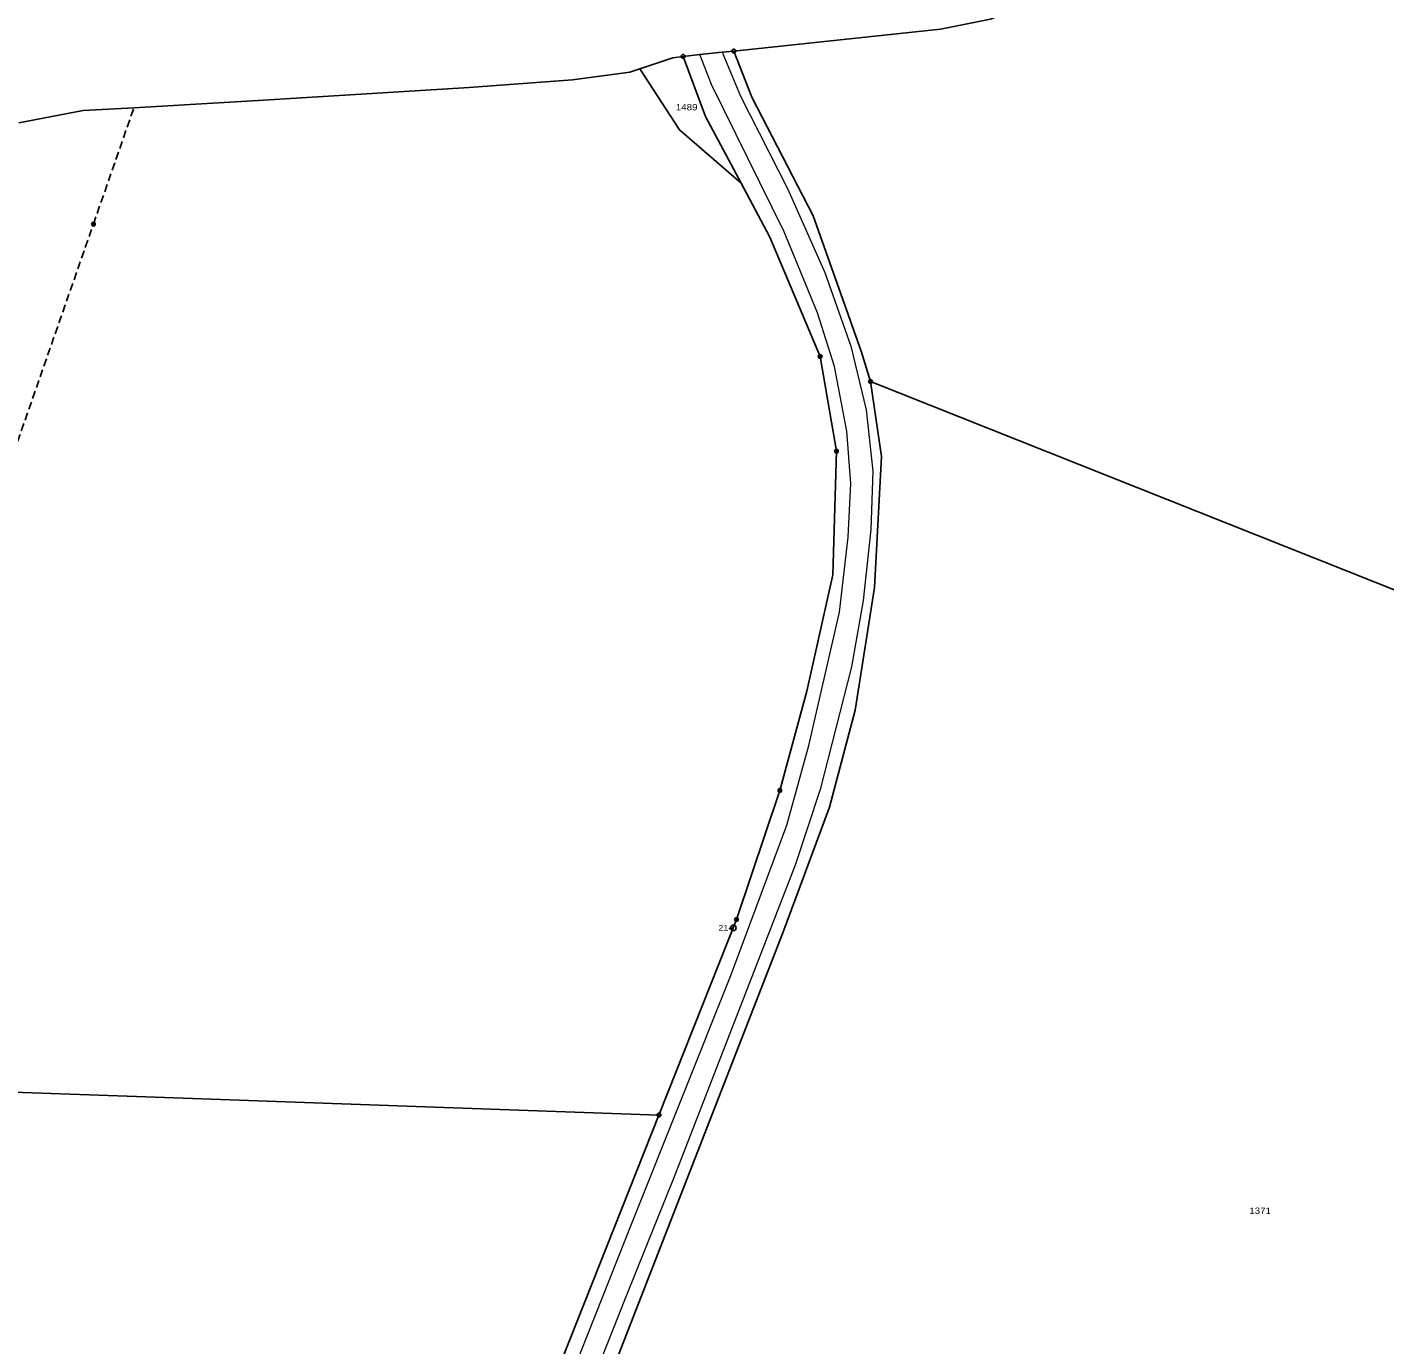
# Model space of a CAD drawing. Extents: x -872229 to -869198, y -1075981 to -1074329.
# Drawn here: x -871207 to -870843.3, y -1074936.4 to -1074583.6 of the extents above; entities that cross this region are included whole.
import ezdxf
from ezdxf.enums import TextEntityAlignment as Align

# ---------------------------------------------------------------- set-up
doc = ezdxf.new("R2010")
doc.units = 0
doc.header["$LTSCALE"] = 0.68
doc.linetypes.add('MEDIUM_DASHED', pattern=[4.5, 3, -1.5])
for name, color, linetype, lineweight in [('1', 7, 'Continuous', 25), ('4', 7, 'Continuous', 13), ('6', 7, 'Continuous', 25), ('8', 7, 'Continuous', 25)]:
    doc.layers.add(name, color=color, linetype=linetype, lineweight=lineweight)
doc.layers.add('2', color=7, linetype='Continuous')

msp = doc.modelspace()

# ---------------------------------------------------------------- linework, layer by layer
at = {"layer": '1'}
for points in [[(-870848.41, -1074534.87), (-870883.9, -1074554.93), (-870908.43, -1074563.86), (-870934.77, -1074575.4), (-870948.95, -1074581.46), (-870962.37, -1074584.16), (-871017.7, -1074589.98)], [(-871031.28, -1074591.41), (-871034.01, -1074591.76), (-871042.88, -1074594.72)], [(-871017.7, -1074589.98), (-871020.82, -1074590.31), (-871026.85, -1074590.94), (-871031.28, -1074591.41)], [(-871015.72, -1074625.4), (-871025.25, -1074607.47), (-871031.28, -1074591.41)], [(-871017.7, -1074589.98), (-871012.91, -1074602.34), (-870996.45, -1074634.07), (-870983.56, -1074670.35), (-870981.09, -1074678.49)], [(-871042.88, -1074594.72), (-871045.55, -1074595.6), (-871060.96, -1074597.73), (-871088.61, -1074599.78), (-871145.12, -1074603.23), (-871154.19, -1074603.78), (-871178.39, -1074605.16), (-871192.01, -1074605.93), (-871209.25, -1074609.21)], [(-871015.72, -1074625.4), (-871032.24, -1074611.11), (-871042.88, -1074594.72)], [(-871037.76, -1074874.85), (-871017, -1074822.52), (-871005.37, -1074787.95), (-870998.12, -1074761.36), (-870991.22, -1074730.22), (-870990.23, -1074697.13), (-870994.58, -1074671.74), (-871008.06, -1074639.82), (-871015.72, -1074625.4)], [(-870981.09, -1074678.49), (-870978.14, -1074698.51), (-870980.02, -1074733.6), (-870985.23, -1074766.42), (-870992.05, -1074792.43), (-871004.56, -1074826.1), (-871074.68, -1075006.03), (-871079.84, -1075019.17), (-871088.25, -1075040.59), (-871096.99, -1075058.79)], [(-870634.05, -1074816.48), (-870806.04, -1074748.1), (-870981.09, -1074678.49)], [(-871282.11, -1074866.22), (-871180.17, -1074869.82), (-871037.76, -1074874.85)], [(-871098, -1075028.09), (-871087.54, -1075000.31), (-871037.76, -1074874.85)]]:
    msp.add_lwpolyline(points, dxfattribs=at)
at = {"layer": '4'}
for p, q in [((-871020.82, -1074590.31), (-871015.88, -1074602.08)), ((-871015.88, -1074602.08), (-871003.35, -1074626.81)), ((-870986.33, -1074668.97), (-870982.28, -1074686.06)), ((-870989.39, -1074740.24), (-870987.11, -1074720.18)), ((-870981.01, -1074718.09), (-870983.08, -1074737.12)), ((-871018.55, -1074837.46), (-871003.48, -1074797.23)), ((-871033.54, -1074890.96), (-871046.65, -1074923.52))]:
    msp.add_line(p, q, dxfattribs=at)
for points in [[(-870987.11, -1074720.18), (-870986.4, -1074705.78), (-870987.43, -1074691.78), (-870990.7, -1074674.48), (-870995.31, -1074660.1), (-871004.24, -1074638.38), (-871023.65, -1074598.94), (-871026.85, -1074590.94)], [(-871003.35, -1074626.81), (-870993.36, -1074649.29), (-870986.33, -1074668.97)], [(-870982.28, -1074686.06), (-870980.48, -1074702.5), (-870981.01, -1074718.09)], [(-870983.08, -1074737.12), (-870986.22, -1074754.84), (-870994.55, -1074787.7), (-871001.25, -1074808), (-871033.54, -1074890.96)], [(-871003.48, -1074797.23), (-870997.63, -1074775.93), (-870989.39, -1074740.24)], [(-871070.54, -1074968.25), (-871044.98, -1074903.65), (-871018.55, -1074837.46)], [(-871046.65, -1074923.52), (-871058.82, -1074954.4), (-871080.04, -1075008.93)]]:
    msp.add_lwpolyline(points, dxfattribs=at)
at = {"layer": '6', "linetype": 'MEDIUM_DASHED'}
msp.add_line((-871189.25, -1074636.33), (-871178.39, -1074605.16), dxfattribs=at)
msp.add_lwpolyline([(-871241.92, -1074787.06), (-871217.63, -1074717.67), (-871189.25, -1074636.33)], dxfattribs=at)
at = {"layer": '6'}
for radius in [0.5, 0.4, 0.3, 0.2, 0.1]:
    msp.add_circle((-871189.2534, -1074636.3299), radius, dxfattribs=at)
at = {"layer": '8'}
for centre, radius in [((-871031.28, -1074591.4099), 0.5), ((-871031.28, -1074591.4099), 0.0303), ((-871017.7, -1074589.9799), 0.5), ((-871017.7, -1074589.9799), 0.0303), ((-870994.58, -1074671.7399), 0.5), ((-870994.58, -1074671.7399), 0.0303), ((-870981.09, -1074678.4899), 0.5), ((-870981.09, -1074678.4899), 0.0303), ((-870990.23, -1074697.1299), 0.5), ((-870990.23, -1074697.1299), 0.0303), ((-871005.37, -1074787.9499), 0.5), ((-871005.37, -1074787.9499), 0.0303), ((-871017, -1074822.5199), 0.5), ((-871017.82, -1074824.7298), 0.75), ((-871017.82, -1074824.7298), 0.03), ((-871017, -1074822.5199), 0.0303), ((-871037.76, -1074874.8499), 0.5), ((-871037.76, -1074874.8499), 0.0303)]:
    msp.add_circle(centre, radius, dxfattribs=at)

# ---------------------------------------------------------------- texts
at = {"layer": '2', "width": 1.15}
for s, p in [('1489', (-871033.25, -1074605.88)), ('1371', (-870879.64, -1074901.33))]:
    msp.add_text(s, height=1.7, dxfattribs=at).set_placement(p)
at = {"layer": '8', "width": 1.2}
msp.add_text('214', height=1.5, dxfattribs=at).set_placement((-871017.82, -1074825.48), align=Align.RIGHT)

doc.saveas('drawing.dxf')
